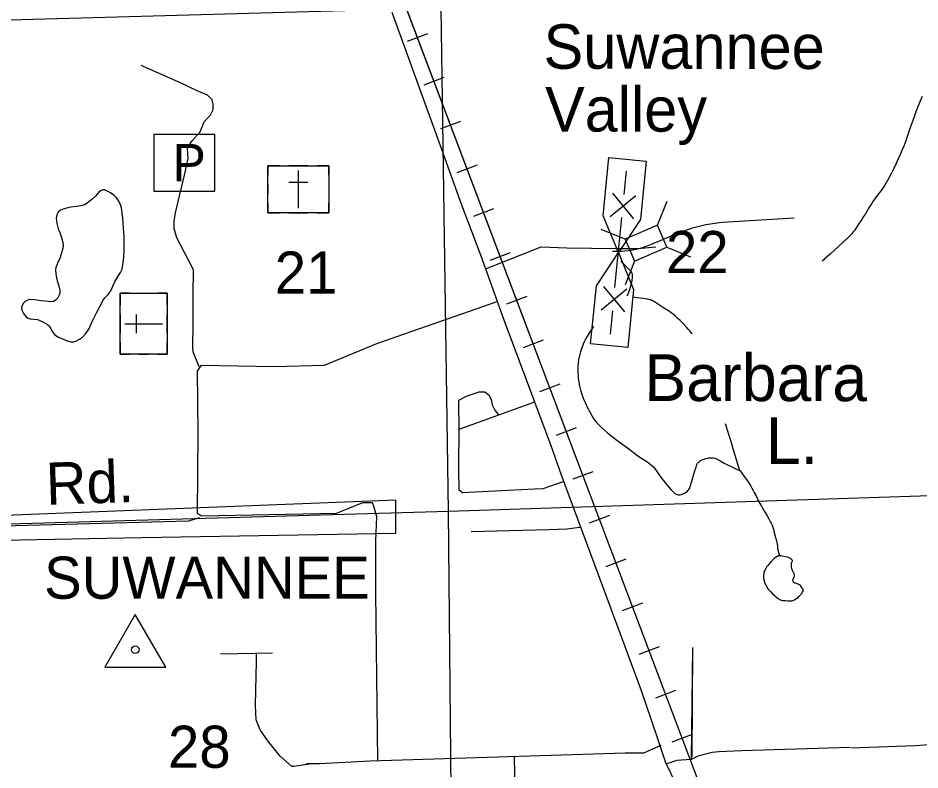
# Model space of a CAD drawing. Extents: x 2480962 to 2688785, y 277103 to 599240.
# Drawn here: x 2528689 to 2538319, y 472131 to 480163 of the extents above; entities that cross this region are included whole.
import ezdxf

# ---------------------------------------------------------------- set-up
doc = ezdxf.new("R2010")
doc.units = 0
for name, color, linetype in [('Communities and Subdivisions Names without Post Office', 7, 'Continuous'), ('Culture', 7, 'Continuous'), ('Lakes and Ponds Text', 7, 'Continuous'), ('Level 31', 7, 'Continuous'), ('Local Roads Improved', 7, 'Continuous'), ('Local Roads Paved', 7, 'Continuous'), ('Local Roads Related Cells', 7, 'Continuous'), ('Local Roads Related Text', 7, 'Continuous'), ('Narrow River Creek and Branch and Slough', 7, 'Continuous'), ('Railroads', 7, 'Continuous'), ('Section Lines', 7, 'Continuous'), ('Section Numbers', 7, 'Continuous'), ('Swamps', 7, 'Continuous'), ('Triangulation Station', 7, 'Continuous'), ('Triangulation Station Text', 7, 'Continuous'), ('Uninventoried Roads and Features', 7, 'Continuous'), ('US Routes Highway Center Lines', 7, 'Continuous')]:
    doc.layers.add(name, color=color, linetype=linetype)

msp = doc.modelspace()

# ---------------------------------------------------------------- linework, layer by layer
at = {"layer": 'Culture'}
for p, q in [((2531356.736, 478584.098), (2531356.736, 478484.098)), ((2531481.736, 478584.098), (2531356.736, 478584.098)), ((2531781.736, 478584.098), (2531581.736, 478584.098)), ((2531681.736, 478534.098), (2531681.736, 478134.098)), ((2532006.736, 478584.098), (2531881.736, 478584.098)), ((2532006.736, 478484.098), (2532006.736, 478584.098)), ((2531581.736, 478409.098), (2531781.736, 478409.098)), ((2531356.736, 478384.098), (2531356.736, 478284.098)), ((2532006.736, 478384.098), (2532006.736, 478284.098)), ((2531356.736, 478184.098), (2531356.736, 478084.098)), ((2532006.736, 478084.098), (2532006.736, 478184.098)), ((2531356.736, 478084.098), (2531481.736, 478084.098)), ((2531581.736, 478084.098), (2531781.736, 478084.098)), ((2531881.736, 478084.098), (2532006.736, 478084.098)), ((2529780.688, 477222.809), (2529780.688, 477097.809)), ((2529880.688, 477222.809), (2529780.688, 477222.809)), ((2529980.688, 477222.809), (2530080.688, 477222.809)), ((2530280.688, 477222.809), (2530180.688, 477222.809)), ((2530280.688, 477097.809), (2530280.688, 477222.809)), ((2529780.688, 476997.809), (2529780.688, 476797.809)), ((2529955.688, 476797.809), (2529955.688, 476997.809)), ((2530280.688, 476797.809), (2530280.688, 476997.809)), ((2529830.688, 476897.809), (2530230.688, 476897.809)), ((2529780.688, 476697.809), (2529780.688, 476572.809)), ((2530280.688, 476572.809), (2530280.688, 476697.809)), ((2529780.688, 476572.809), (2529880.688, 476572.809)), ((2529980.688, 476572.809), (2530080.688, 476572.809)), ((2530180.688, 476572.809), (2530280.688, 476572.809))]:
    msp.add_line(p, q, dxfattribs=at)
for points in [[(2531356.736, 478584.098), (2532006.736, 478584.098), (2532006.736, 478084.098), (2531356.736, 478084.098)], [(2529780.688, 476572.809), (2529780.688, 477222.809), (2530280.688, 477222.809), (2530280.688, 476572.809)]]:
    msp.add_lwpolyline(points, close=True, dxfattribs=at)
at = {"layer": 'Level 31'}
msp.add_lwpolyline([(2532724.12, 474659.966), (2532724.12, 475013.62), (2528550.997, 474848.582), (2525438.837, 474848.582), (2523010.409, 474754.274), (2519426.71, 474683.543), (2515159.279, 474542.081), (2513461.737, 474518.504), (2512471.505, 474518.504), (2512259.312, 474447.773), (2512471.505, 474235.58), (2513815.392, 474141.273), (2516314.551, 474212.004), (2521548.637, 474400.619), (2527395.725, 474565.658), (2530012.769, 474612.812)], close=True, dxfattribs=at)
at = {"layer": 'Local Roads Improved'}
for p, q in [((2530852.474, 473372.475), (2531406.426, 473380.997)), ((2534035.535, 470286.718), (2533989.388, 472271.01))]:
    msp.add_line(p, q, dxfattribs=at)
for points in [[(2530623.749, 476437.682), (2530559.676, 476599.259), (2530554.104, 476652.19), (2530559.676, 476900.127), (2530559.676, 477290.142), (2530562.462, 477396.002), (2530562.462, 477474.005), (2530509.531, 477577.08), (2530384.169, 477813.875), (2530356.311, 477914.164), (2530356.311, 477997.739), (2530370.24, 478081.313), (2530414.813, 478262.391), (2530467.744, 478485.256), (2530506.745, 478663.548), (2530498.388, 478769.409), (2530545.747, 478847.412), (2530632.107, 478947.702), (2530676.68, 479053.563), (2530743.54, 479128.78), (2530774.183, 479187.282), (2530774.183, 479242.998), (2530760.254, 479290.357), (2530712.896, 479340.502), (2530601.463, 479385.075), (2530431.528, 479465.863), (2530189.162, 479574.51), (2530002.513, 479658.084)], [(2533438.476, 475086.698), (2533398.048, 475118.463), (2533395.16, 475349.481), (2533398.048, 475805.744), (2533395.16, 476022.324), (2533395.16, 476082.966), (2533484.68, 476129.17), (2533611.74, 476169.598), (2533672.383, 476169.598), (2533718.586, 476134.945), (2533741.688, 476088.742), (2533750.351, 476030.987), (2533779.229, 475976.12), (2533816.769, 475927.029), (2533816.769, 475921.253)], [(2538584.242, 473998.2), (2538610.612, 472521.518), (2538604.019, 472442.41), (2538564.465, 472409.448), (2538267.811, 472389.671), (2537582.208, 472363.302)], [(2531798.454, 472192.13), (2531632.268, 472166.563), (2531610.962, 472166.563), (2531487.388, 472277.354), (2531355.292, 472443.539), (2531274.33, 472558.591), (2531231.718, 472665.12), (2531223.196, 472822.784), (2531235.979, 473291.512), (2531235.979, 473368.213)]]:
    msp.add_lwpolyline(points, dxfattribs=at)
at = {"layer": 'Local Roads Paved'}
for p, q in [((2534203.07, 476060.088), (2533396.11, 475769.053)), ((2535881.387, 472244.64), (2535894.572, 473437.852)), ((2535887.979, 472271.01), (2535894.572, 473431.26))]:
    msp.add_line(p, q, dxfattribs=at)
for points in [[(2533691.554, 477488.804), (2534273.624, 477718.105), (2534547.02, 477709.285), (2535076.175, 477700.466), (2535305.475, 477700.466), (2535499.498, 477718.105)], [(2532531.375, 472230.481), (2532509.776, 474022.844), (2532509.776, 474578.456), (2532518.595, 474834.214), (2532492.138, 474940.044), (2532474.499, 474984.141), (2532368.668, 474984.141), (2532192.283, 474913.587), (2532086.453, 474869.491), (2531557.298, 474860.671), (2530648.917, 474843.033), (2530604.82, 474869.491), (2530613.64, 475733.776), (2530607.035, 476390.323), (2530648.822, 476454.397), (2531425.01, 476439.315), (2531962.983, 476456.954), (2532518.595, 476686.254), (2533806.204, 477136.035)], [(2534516.153, 475213.441), (2534291.262, 475134.068), (2534203.07, 475129.658), (2533431.386, 475089.972)], [(2530622.459, 474825.394), (2530507.809, 474790.117), (2528532.299, 474737.202), (2527650.375, 474719.563), (2524678.292, 474640.19), (2523328.948, 474640.19), (2522173.628, 474622.552), (2521115.319, 474587.275), (2520365.684, 474569.636)], [(2534688.128, 474719.563), (2534547.02, 474701.925), (2534357.407, 474697.515), (2533528.398, 474675.467)], [(2535552.413, 472391.284), (2535367.209, 472311.911), (2535173.186, 472311.911), (2532448.041, 472223.719), (2531910.068, 472197.261), (2531768.96, 472197.261)], [(2537569.024, 472369.894), (2536415.366, 472336.933), (2536171.45, 472323.748), (2536098.934, 472317.156), (2535947.31, 472277.602), (2535874.795, 472244.64), (2535723.171, 472231.456), (2535617.694, 472198.494)]]:
    msp.add_lwpolyline(points, dxfattribs=at)
at = {"layer": 'Local Roads Related Cells'}
for p, q in [((2530138.357, 478917.791), (2530138.357, 478314.588)), ((2530791.559, 478917.791), (2530138.357, 478917.791)), ((2530791.559, 478314.588), (2530791.559, 478917.791)), ((2534937.379, 478050.764), (2534998.663, 478672.753)), ((2534998.663, 478672.753), (2535396.736, 478633.53)), ((2535396.736, 478633.53), (2535335.451, 478011.542)), ((2535160.928, 478279.949), (2535185.442, 478528.744)), ((2530138.357, 478314.588), (2530791.559, 478314.588)), ((2535012.017, 478043.41), (2535285.326, 478267.692)), ((2535036.531, 478292.206), (2535260.812, 478018.896)), ((2535099.644, 477657.961), (2534937.379, 478050.764)), ((2535062.873, 477284.77), (2535136.415, 478031.153)), ((2535335.451, 478011.542), (2535099.644, 477657.961)), ((2534863.837, 477304.381), (2535099.644, 477657.961)), ((2535099.644, 477657.961), (2535261.91, 477265.159)), ((2534802.553, 476682.393), (2534863.837, 477304.381)), ((2534916.26, 477048.005), (2535189.569, 477272.286)), ((2534938.476, 477297.027), (2535162.757, 477023.717)), ((2535261.91, 477265.159), (2535200.625, 476643.17)), ((2535013.846, 476787.179), (2535038.359, 477035.974)), ((2535200.625, 476643.17), (2534802.553, 476682.393))]:
    msp.add_line(p, q, dxfattribs=at)
at = {"layer": 'Narrow River Creek and Branch and Slough'}
for points in [[(2538343.925, 479326.311), (2538318.777, 479269.789), (2538301.093, 479227.14), (2538275.989, 479162.721), (2538252.002, 479097.732), (2538225.428, 479021.913), (2538186.621, 478907.894), (2538166.553, 478851.126), (2538145.34, 478794.746), (2538126.132, 478747.634), (2538111, 478712.626), (2538087.489, 478660.449), (2538063.444, 478608.441), (2538035.95, 478550.044), (2538014.713, 478506.6), (2537998.271, 478474.29), (2537972.527, 478426.377), (2537945.172, 478379.268), (2537930.357, 478356.208), (2537916.579, 478336.603), (2537891.252, 478303.157), (2537852.378, 478253.654), (2537833.502, 478228.538), (2537815.589, 478202.77), (2537800.298, 478179.077), (2537774.393, 478137.038), (2537736.227, 478073.458), (2537716.817, 478041.841), (2537696.794, 478010.588), (2537663.636, 477959.908), (2537638.22, 477922.206), (2537618.371, 477894.566), (2537602.84, 477874.387), (2537590.745, 477859.646), (2537571.755, 477838.285), (2537551.589, 477817.983), (2537502.251, 477772), (2537452.502, 477726.543), (2537363.916, 477645.744), (2537275.158, 477565.137)], [(2529799.636, 477479.731), (2529815.659, 477572.136), (2529823.43, 477665.107), (2529823.837, 477744.386), (2529821.189, 477823.639), (2529815.137, 477923.985), (2529807.786, 478024.276), (2529802.786, 478071.831), (2529795.877, 478119.226), (2529781.684, 478170.262), (2529757.484, 478219.037), (2529741.104, 478242.324), (2529711.524, 478271.363), (2529677.134, 478297.036), (2529652.651, 478311.992), (2529612.514, 478326.58), (2529593.385, 478327.326), (2529576.404, 478321.851), (2529550.53, 478301.53), (2529515.056, 478262.095), (2529477.391, 478225.126), (2529430.284, 478188.356), (2529405.239, 478172.08), (2529377.931, 478160.107), (2529314.895, 478149.283), (2529251.388, 478142.225), (2529206.408, 478133.079), (2529161.894, 478119.651), (2529143, 478109.811), (2529119.507, 478088.177), (2529104.615, 478060.592), (2529098.039, 478023.973), (2529102.676, 477967.493), (2529117.271, 477912.799), (2529133.997, 477871.073), (2529150.158, 477828.756), (2529166.156, 477765.442), (2529169.802, 477733.538), (2529167.797, 477702.185), (2529154.832, 477654.057), (2529137.45, 477606.558), (2529113.077, 477553.559), (2529091.407, 477500.11), (2529087.729, 477472.916), (2529091.235, 477430.867), (2529098.258, 477389.222), (2529106.721, 477354.689), (2529125.056, 477303.466), (2529137.174, 477252.42), (2529135.901, 477224.09), (2529130.098, 477203.183), (2529113.175, 477173.195), (2529085.849, 477145.888), (2529067.452, 477135.812), (2529039.798, 477132.311), (2529012.052, 477134.134), (2528937.955, 477143.584), (2528863.858, 477152.905), (2528813.654, 477155.958), (2528788.67, 477151.036), (2528763.725, 477135.446), (2528747.307, 477118.14), (2528732.322, 477092.153), (2528727.722, 477066.157), (2528730.777, 477042.562), (2528746.626, 477007.156), (2528776.605, 476971.799), (2528791.484, 476960.494), (2528818.259, 476950.705), (2528858.989, 476948.19), (2528898.538, 476942.037), (2528953.047, 476919.628), (2529004.924, 476890.884), (2529027.382, 476866.745), (2529050.514, 476820.917), (2529063.259, 476799.021), (2529080.441, 476781.095), (2529121.569, 476755.659), (2529165.624, 476734.889), (2529224.043, 476711.314), (2529253.613, 476704.629), (2529282.275, 476705.043), (2529306.5, 476711.517), (2529347.342, 476732.249), (2529375.907, 476754.178), (2529413.9, 476794.407), (2529444.148, 476839.773), (2529486.037, 476927.914), (2529526.193, 477015.51), (2529561.387, 477082.605), (2529598.273, 477148.803), (2529617.541, 477175.295), (2529651.442, 477211.59), (2529681.364, 477250.559), (2529702.533, 477298.192), (2529722.274, 477346.353), (2529762.184, 477412.249), (2529782.627, 477445.128), (2529799.636, 477479.731)], [(2535886.722, 476788.955), (2535872.388, 476807.314), (2535861.403, 476820.803), (2535844.491, 476840.653), (2535826.978, 476860.119), (2535788.054, 476902.163), (2535758.332, 476933.098), (2535735.398, 476955.534), (2535717.691, 476971.747), (2535704.065, 476983.487), (2535682.976, 477000.305), (2535660.996, 477016.03), (2535633.19, 477034.437), (2535591.186, 477061.435), (2535549.029, 477088.236), (2535504.705, 477117.757), (2535493.522, 477124.994), (2535485.005, 477130.272), (2535471.937, 477137.857), (2535458.415, 477144.928), (2535451.233, 477148.205), (2535444.403, 477150.895), (2535437.923, 477153.112), (2535425.597, 477156.568), (2535414.653, 477158.961), (2535404.982, 477160.669), (2535336.556, 477169.405), (2535295.179, 477176.259), (2535253.755, 477182.838)], [(2534832.79, 476867.428), (2534795.979, 476813.733), (2534778.258, 476786.456), (2534761.22, 476758.492), (2534750.653, 476739.5), (2534734.173, 476705.566), (2534723.202, 476679.556), (2534708.384, 476639.691), (2534694.797, 476598.862), (2534686.058, 476568.595), (2534680.696, 476545.792), (2534674.425, 476511.432), (2534670.106, 476476.898), (2534667.73, 476446.722), (2534666.617, 476420.189), (2534666.84, 476373.573), (2534668.822, 476338.551), (2534671.329, 476312.302), (2534676.732, 476273.032), (2534684.106, 476233.986), (2534691.018, 476204.496), (2534697.897, 476179.103), (2534711.76, 476135.439), (2534723.639, 476103.208), (2534743.762, 476055.434), (2534766.548, 476008.026), (2534796.159, 475951.1), (2534819.659, 475909.764), (2534838.647, 475879.911), (2534853.923, 475858.333), (2534866.076, 475842.672), (2534885.594, 475820.128), (2534906.868, 475798.849), (2534949.74, 475760.433), (2534982.414, 475732.73), (2535032.294, 475692.587), (2535083.263, 475653.676), (2535195.213, 475570.603), (2535307.496, 475488.127), (2535344.942, 475462.508), (2535402.174, 475425.571), (2535430.111, 475406.063), (2535456.885, 475384.805), (2535472.262, 475370.1), (2535484.502, 475356.187), (2535503.95, 475330.135), (2535530.925, 475289.102), (2535544.619, 475268.709), (2535559.185, 475249.018), (2535591.271, 475208.912), (2535640.587, 475150.11), (2535666.433, 475121.217), (2535693.476, 475092.6), (2535701.008, 475086.031), (2535708.492, 475081.155), (2535715.566, 475077.584), (2535728.718, 475072.964), (2535738.875, 475070.922), (2535746.459, 475070.224), (2535757.486, 475070.568), (2535767.722, 475072.646), (2535781.541, 475077.468), (2535793.97, 475082.826), (2535804.832, 475088.366), (2535823.126, 475099.929), (2535835.649, 475110.121), (2535844.032, 475118.596), (2535849.61, 475125.411), (2535856.625, 475136.356), (2535861.75, 475148.149), (2535882.343, 475214.546), (2535902.138, 475280.935), (2535919.151, 475336.783), (2535927.983, 475364.66), (2535937.543, 475392.499), (2535940.907, 475400.249), (2535944.855, 475407.02), (2535954.108, 475418.49), (2535963.905, 475427.29), (2535973.545, 475434.105), (2535982.642, 475439.433), (2535999.65, 475447.437), (2536012.971, 475452.432), (2536033.171, 475458.49), (2536052.774, 475463.056), (2536064.573, 475465.091), (2536085.898, 475466.791), (2536102.066, 475466.31), (2536114.071, 475464.844), (2536131.554, 475460.701), (2536139.935, 475457.688), (2536147.998, 475454.008), (2536173.496, 475440.14), (2536211.046, 475418.205), (2536229.941, 475407.512), (2536249.178, 475397.486), (2536323.222, 475360.903), (2536360.481, 475343.012), (2536398.118, 475325.873)], [(2536395.993, 475326.895), (2536361.452, 475444.856), (2536326.09, 475562.57), (2536309.708, 475615.224), (2536284.376, 475693.968), (2536259.718, 475772.932), (2536255.6, 475787.008), (2536249.706, 475808.201), (2536244.054, 475829.462)], [(2536398.118, 475325.873), (2536436.09, 475275.196), (2536463.455, 475236.66), (2536483.265, 475207.357), (2536511.7, 475162.603), (2536525.293, 475139.807), (2536538.438, 475116.696), (2536549.689, 475095.89), (2536568.566, 475059.089), (2536596.274, 475003.636), (2536610.491, 474976.121), (2536625.339, 474948.947), (2536641.344, 474921.346), (2536665.935, 474880.259), (2536690.291, 474838.99), (2536705.201, 474813.442), (2536716.264, 474794.209), (2536724.227, 474779.619), (2536729.897, 474768.529), (2536733.933, 474760.106), (2536739.566, 474747.27), (2536744.606, 474734.148), (2536749.651, 474719.22), (2536753.729, 474706.085), (2536760.277, 474682.967), (2536778.015, 474613.115), (2536786.633, 474578.928), (2536794.833, 474544.671), (2536795.578, 474541.111), (2536796.597, 474534.389), (2536797.175, 474528.466), (2536798.269, 474507.553), (2536798.633, 474502.309), (2536799.5, 474494.453), (2536800.134, 474490.535), (2536800.937, 474486.627), (2536801.49, 474484.242), (2536802.079, 474481.753), (2536803.355, 474476.498), (2536804.696, 474471.155), (2536806.063, 474465.881), (2536808.856, 474455.622), (2536811.475, 474446.648), (2536813.841, 474439.131), (2536815.93, 474433.035), (2536817.746, 474428.216), (2536819.308, 474424.496), (2536820.642, 474421.687), (2536821.777, 474419.617), (2536822.739, 474418.132), (2536823.555, 474417.102), (2536824.246, 474416.422), (2536824.831, 474416.004), (2536825.808, 474415.695), (2536826.498, 474415.836), (2536826.99, 474416.163), (2536827.683, 474417.025), (2536828.318, 474418.353)], [(2536824.374, 474428.187), (2536807.019, 474418.947), (2536794.679, 474411.482), (2536777.024, 474399.247), (2536760.101, 474385.548), (2536746.213, 474372.836), (2536726.735, 474352.93), (2536708.028, 474331.859), (2536694.728, 474315.522), (2536685.508, 474302.96), (2536672.83, 474283.333), (2536661.463, 474262.4), (2536656.336, 474250.471), (2536652.872, 474239.657), (2536650.593, 474229.981), (2536648.224, 474212.757), (2536647.735, 474199.761), (2536648.942, 474180.468), (2536652.318, 474161.828), (2536659.36, 474137.136), (2536666.138, 474118.918), (2536672.173, 474105.523), (2536682.923, 474086.012), (2536689.125, 474076.575), (2536695.918, 474067.386), (2536712.447, 474047.555), (2536725.175, 474033.714), (2536744.926, 474013.938), (2536765.63, 473994.504), (2536790.544, 473971.735), (2536803.936, 473961.611), (2536811.226, 473957.109), (2536819.047, 473953.074), (2536829.43, 473948.88), (2536838.594, 473946.109), (2536854.773, 473942.855), (2536879.25, 473940.374), (2536903.783, 473938.573), (2536927.52, 473936.67), (2536939.436, 473937.059), (2536951.319, 473939.334), (2536961.127, 473942.552), (2536979.259, 473950.303), (2536994.639, 473958.712), (2537007.549, 473967.138), (2537018.308, 473975.208), (2537027.231, 473982.724), (2537041.543, 473996.695), (2537051.015, 474007.68), (2537057.31, 474016.105), (2537065.307, 474028.895), (2537071.385, 474041.682), (2537072.423, 474045.284), (2537072.587, 474052.432), (2537071.073, 474059.005), (2537068.687, 474064.917), (2537062.663, 474075.407), (2537050.961, 474090.773), (2537038.797, 474104.587), (2537034.909, 474108.301), (2537026.407, 474113.817), (2537018.015, 474117.475), (2536986.828, 474127.446), (2536979.791, 474130.58), (2536975.007, 474133.426), (2536968.861, 474138.753), (2536964.251, 474145.679), (2536962.686, 474150.055), (2536962.038, 474154.246), (2536962.603, 474162.299), (2536964.569, 474169.505), (2536975.714, 474195.169), (2536978.021, 474201.524), (2536979.917, 474210.876), (2536979.892, 474215.441), (2536979.051, 474219.914), (2536976.312, 474227.8), (2536970.035, 474241.404), (2536959.57, 474261.803), (2536955.054, 474272.215), (2536951.745, 474282.903), (2536949.028, 474297.177), (2536946.655, 474319.063), (2536945.642, 474340.947), (2536946.365, 474345.104), (2536950.397, 474352.4), (2536954.185, 474357.798), (2536956.588, 474361.756), (2536957.778, 474364.651), (2536958.031, 474368.846), (2536957.258, 474370.865), (2536955.757, 474372.823), (2536948.722, 474379.433), (2536941.948, 474384.888), (2536928.826, 474393.376), (2536916.951, 474399.185), (2536906.304, 474403.228), (2536887.216, 474408.482), (2536828.318, 474418.353)]]:
    msp.add_lwpolyline(points, dxfattribs=at)
at = {"layer": 'Railroads'}
for p, q in [((2532692.134, 480644.963), (2535189.55, 474029.408)), ((2533060.411, 479995.026), (2532845.233, 479913.795)), ((2533237.001, 479527.248), (2533021.823, 479446.017)), ((2533413.59, 479059.47), (2533198.412, 478978.239)), ((2533590.179, 478591.692), (2533375.001, 478510.461)), ((2533766.768, 478123.914), (2533551.591, 478042.683)), ((2533943.358, 477656.136), (2533728.18, 477574.905)), ((2534119.947, 477188.358), (2533904.769, 477107.127)), ((2534296.536, 476720.58), (2534081.358, 476639.349)), ((2534473.126, 476252.802), (2534257.948, 476171.571)), ((2534649.715, 475785.024), (2534434.537, 475703.793)), ((2534826.304, 475317.246), (2534611.126, 475236.015)), ((2535002.893, 474849.468), (2534787.716, 474768.237)), ((2535179.483, 474381.69), (2534964.305, 474300.459)), ((2535356.072, 473913.912), (2535140.894, 473832.681)), ((2535532.661, 473446.134), (2535317.483, 473364.903)), ((2535709.25, 472978.356), (2535494.072, 472897.125)), ((2535885.839, 472510.578), (2535670.661, 472429.347))]:
    msp.add_line(p, q, dxfattribs=at)
for points in [[(2522053.314, 488277.525), (2530907.987, 482809.816), (2531282.344, 482550.647), (2531627.559, 482253.766), (2531939.85, 481922.425), (2532215.797, 481560.258), (2532452.375, 481171.229), (2532646.991, 480759.603), (2532692.134, 480644.963), (2535189.55, 474029.408), (2536089.7, 471644.944), (2536291.253, 471185.4), (2536531.488, 470762.342), (2552586.883, 445559.036)], [(2535189.55, 474029.408), (2536089.7, 471644.944), (2536291.253, 471185.4), (2536531.488, 470762.342), (2552586.883, 445559.036), (2552586.884, 445559.036), (2553075.384, 444874.143), (2553427.841, 444460.531), (2556691.947, 440882.519), (2556841.764, 440734.641), (2557006.218, 440603.234), (2557183.506, 440489.737), (2557371.687, 440395.394), (2557568.699, 440321.239), (2557735.519, 440276.028), (2568072.12, 437946.462), (2568887.934, 437807.005), (2569361.53, 437765.755), (2570495.789, 437701.245), (2571983.523, 437694.622), (2573132.142, 437796.523), (2616563.163, 443432.973)]]:
    msp.add_lwpolyline(points, dxfattribs=at)
at = {"layer": 'Section Lines'}
for p, q in [((2533199.703, 480269.467), (2527878.024, 480119.717)), ((2533286.716, 474891.598), (2533207.744, 480269.714)), ((2538560.675, 475064.088), (2533286.709, 474891.598)), ((2533286.715, 474891.598), (2527958.459, 474740.156)), ((2533333.473, 469635.457), (2533286.709, 474891.598))]:
    msp.add_line(p, q, dxfattribs=at)
at = {"layer": 'Swamps'}
msp.add_lwpolyline([(2535124.882, 477567.72), (2535142.087, 477549.28), (2535168.299, 477522.009), (2535194.593, 477494.839), (2535199.183, 477490.293), (2535203.288, 477486.519), (2535210.591, 477480.115), (2535216.094, 477475.259), (2535220.195, 477471.461), (2535223.239, 477468.473), (2535225.496, 477466.131), (2535228.831, 477462.423), (2535232.09, 477458.439), (2535235.642, 477453.425), (2535238.487, 477448.577), (2535240.753, 477443.915), (2535242.546, 477439.454), (2535243.954, 477435.2), (2535245.047, 477431.156), (2535246.551, 477423.456), (2535247.34, 477416.62), (2535247.673, 477410.589), (2535247.722, 477405.289), (2535247.345, 477396.008), (2535246.744, 477389.078), (2535245.471, 477378.807), (2535243.924, 477368.774), (2535242.083, 477358.141), (2535238.397, 477339.548), (2535235.255, 477325.615), (2535229.959, 477304.738), (2535223.992, 477283.886), (2535217.008, 477260.663), (2535211.505, 477243.643), (2535206.89, 477231.029), (2535203.014, 477221.621), (2535199.811, 477214.581), (2535194.444, 477204.029), (2535191.473, 477198.748), (2535188.288, 477193.459)], dxfattribs=at)
at = {"layer": 'Triangulation Station'}
msp.add_lwpolyline([(2529941.063, 473790.728), (2529616.071, 473227.808), (2530266.071, 473227.817)], close=True, dxfattribs=at)
msp.add_circle((2529941.068, 473415.451), 40, dxfattribs=at)
at = {"layer": 'Uninventoried Roads and Features'}
for p, q in [((2535516.257, 477950.372), (2535618.369, 478205.663)), ((2536210.565, 477981.729), (2536974.709, 478030.421)), ((2535516.257, 477950.372), (2535171.58, 477802.647)), ((2535617.104, 477715.073), (2535516.257, 477950.372)), ((2535171.581, 477802.647), (2534916.29, 477904.76)), ((2535453.682, 477747.774), (2535751.971, 477873.643)), ((2535171.58, 477802.647), (2535272.427, 477567.348)), ((2535272.427, 477567.348), (2535617.104, 477715.073)), ((2535615.342, 477715.777), (2535870.632, 477613.665)), ((2535272.427, 477567.348), (2535170.315, 477312.057))]:
    msp.add_line(p, q, dxfattribs=at)
for points in [[(2535751.971, 477873.643), (2535890.792, 477923.835), (2536034.099, 477959.242), (2536180.322, 477979.476), (2536210.565, 477981.729)], [(2535034.498, 477673.242), (2535135.103, 477673.743), (2535235.106, 477684.76), (2535333.409, 477706.168), (2535428.936, 477737.735), (2535453.682, 477747.774)]]:
    msp.add_lwpolyline(points, dxfattribs=at)
at = {"layer": 'US Routes Highway Center Lines'}
msp.add_lwpolyline([(2532679.7, 480227.278), (2533211.878, 478763.786), (2533424.75, 478167.746), (2533626.978, 477635.567), (2533877.102, 476938.413), (2534377.35, 475597.322), (2534489.108, 475283.337), (2535058.539, 473750.662), (2535340.594, 472979.002), (2535510.891, 472489.398), (2535601.361, 472212.665), (2535713.119, 471983.828)], dxfattribs=at)

# ---------------------------------------------------------------- texts
at = {"layer": 'Communities and Subdivisions Names without Post Office'}
for s, rotation, p in [('Suwannee', 359.9502306, (2534300.185, 479621.758)), ('Valley', 359.9502333, (2534315.657, 478951.248))]:
    msp.add_text(s, height=475, rotation=rotation, dxfattribs=at).set_placement(p)
at = {"layer": 'Lakes and Ponds Text'}
for s, rotation, p in [('Barbara', 359.9502361, (2535376.297, 476072.504)), ('L.', 359.9502389, (2536674.467, 475399.835))]:
    msp.add_text(s, height=500, rotation=rotation, dxfattribs=at).set_placement(p)
at = {"layer": 'Local Roads Related Cells'}
msp.add_text('P', height=400, rotation=360, dxfattribs=at).set_placement((2530337.764, 478417.844))
at = {"layer": 'Local Roads Related Text'}
msp.add_text('Rd.', height=450, rotation=1.9100528, dxfattribs=at).set_placement((2528993.632, 474963.034))
at = {"layer": 'Section Numbers'}
for s, rotation, p in [('22', 359.979425, (2535606.907, 477438.569)), ('21', 359.979425, (2531430.172, 477219.748)), ('28', 359.9794306, (2530289.959, 472154.499))]:
    msp.add_text(s, height=450, rotation=rotation, dxfattribs=at).set_placement(p)
at = {"layer": 'Triangulation Station Text'}
msp.add_text('SUWANNEE', height=450, rotation=0.0009306, dxfattribs=at).set_placement((2528967.521, 473960.176))

doc.saveas('drawing.dxf')
